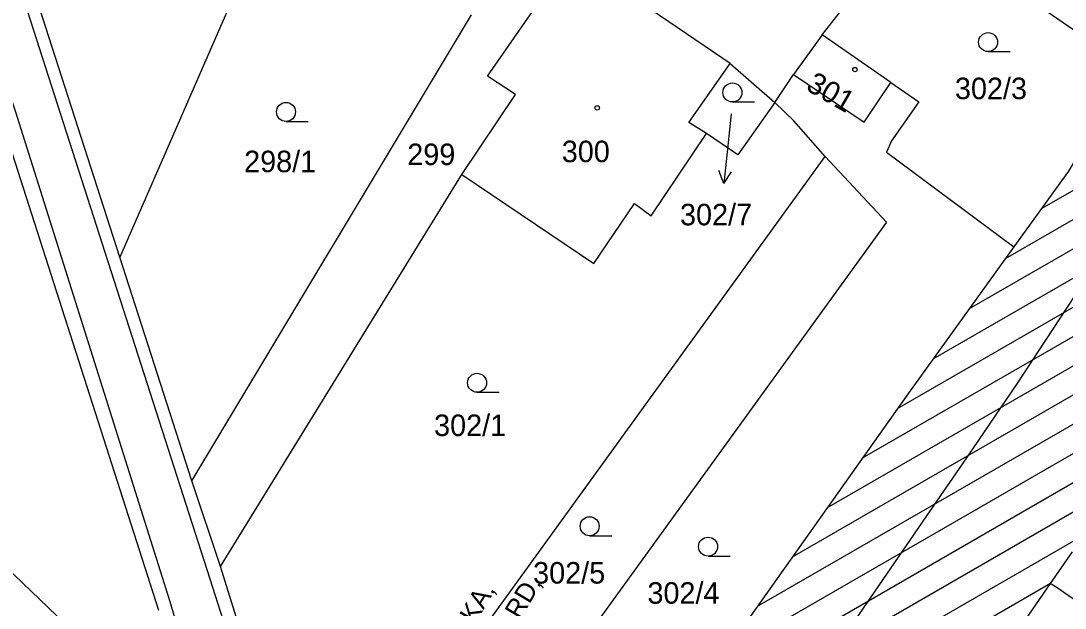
# Model space of a CAD drawing. Extents: x -558500 to -557517, y -1073973 to -1073051.
# Drawn here: x -558169.6 to -558087.2, y -1073349.6 to -1073303.2 of the extents above; entities that cross this region are included whole.
import ezdxf

# ---------------------------------------------------------------- set-up
doc = ezdxf.new("R2010")
doc.units = 0
for name, color, linetype in [('Hranice parcel', 7, 'Continuous'), ('Kolej', 7, 'Continuous'), ('Parcelní čísla', 7, 'Continuous'), ('Pop  PČ popisy', 7, 'Continuous'), ('Svazek obcí údolí Desné', 7, 'Continuous'), ('trasa_NN_popisky', 7, 'Continuous'), ('Značky budov', 7, 'Continuous'), ('Značky kultur', 7, 'Continuous')]:
    doc.layers.add(name, color=color, linetype=linetype)

msp = doc.modelspace()

# ---------------------------------------------------------------- linework, layer by layer
at = {"layer": 'Hranice parcel'}
for p, q in [((-558149, -1073292.52), (-558161.8, -1073321.91)), ((-558161.8, -1073321.91), (-558170.97, -1073293.42)), ((-558106.35, -1073304.33), (-558099.14, -1073295.15)), ((-558099.14, -1073295.15), (-558082.18, -1073306.93)), ((-558156.12, -1073339.58), (-558134.04, -1073302.76)), ((-558106.35, -1073304.33), (-558108.61, -1073307.47)), ((-558100.91, -1073308.09), (-558106.35, -1073304.33)), ((-558113.61, -1073306.59), (-558110.09, -1073309.68)), ((-558110.09, -1073309.68), (-558108.61, -1073307.47)), ((-558171.18, -1073310.99), (-558158.75, -1073349.79)), ((-558146.53, -1073369.85), (-558106.1, -1073313.94)), ((-558101.25, -1073313.61), (-558091.21, -1073321.1)), ((-558153.86, -1073346.35), (-558134.81, -1073315.38)), ((-558156.12, -1073339.58), (-558161.8, -1073321.91)), ((-558179.03, -1073338.54), (-558163.3, -1073353.56)), ((-558153.86, -1073346.35), (-558156.12, -1073339.58)), ((-558146.53, -1073369.85), (-558153.86, -1073346.35))]:
    msp.add_line(p, q, dxfattribs=at)
for points in [[(-558140.29, -1073392.34), (-558154.66, -1073347.35), (-558171.71, -1073294.39)], [(-558134.81, -1073315.38), (-558130.55, -1073309.06), (-558132.76, -1073307.6), (-558126.22, -1073298.15)], [(-558113.61, -1073306.59), (-558124.02, -1073299.5), (-558124.12, -1073299.64), (-558126.22, -1073298.15)], [(-558172.36, -1073303.47), (-558170.06, -1073310.34), (-558157.85, -1073349.12), (-558143.83, -1073396.83)], [(-558115.48, -1073312.12), (-558116.87, -1073311.27), (-558113.61, -1073306.59)], [(-558108.61, -1073307.47), (-558103.03, -1073311.24), (-558100.91, -1073308.09)], [(-558100.91, -1073308.09), (-558098.7, -1073309.62), (-558100.86, -1073312.72), (-558101.25, -1073313.61)], [(-558110.09, -1073309.68), (-558113.01, -1073313.83), (-558115.48, -1073312.12)], [(-558106.1, -1073313.94), (-558108.58, -1073311.13), (-558110.09, -1073309.68)], [(-558134.81, -1073315.38), (-558124.37, -1073322.4), (-558121.16, -1073317.67), (-558119.85, -1073318.64), (-558115.48, -1073312.12)], [(-558106.1, -1073313.94), (-558101.27, -1073319.14), (-558143.89, -1073378.07)], [(-558100.88, -1073366.68), (-558093.95, -1073371.49), (-558091.09, -1073367.38), (-558089.54, -1073368.47), (-558085.38, -1073362.53), (-558086.24, -1073361.96), (-558080.2, -1073353.3), (-558087.87, -1073347.97), (-558088.33, -1073347.7)]]:
    msp.add_lwpolyline(points, dxfattribs=at)
at = {"layer": 'Kolej'}
msp.add_lwpolyline([(-558164.779, -1073439.38), (-558155.66, -1073426.127), (-558147.216, -1073413.854), (-558143.692, -1073408.727), (-558141.06, -1073404.904), (-558137.302, -1073399.438), (-558134.569, -1073395.461), (-558131.717, -1073391.307), (-558124.893, -1073381.375), (-558115.4, -1073367.564), (-558106.183, -1073354.164), (-558097.487, -1073341.511), (-558095.261, -1073338.268), (-558090.946, -1073331.927), (-558084.696, -1073322.399), (-558079.035, -1073313.091), (-558073.774, -1073303.7), (-558068.675, -1073293.768)], dxfattribs=at)
at = {"layer": 'Pop  PČ popisy'}
for p, q in [((-558113.53, -1073310.57), (-558113.79, -1073313.11)), ((-558113.79, -1073313.11), (-558114.104, -1073316.095)), ((-558114.104, -1073316.095), (-558114.497, -1073315.046)), ((-558114.104, -1073316.095), (-558113.501, -1073315.151))]:
    msp.add_line(p, q, dxfattribs=at)
at = {"layer": 'Svazek obcí údolí Desné'}
for p, q in [((-558089.021, -1073318.064), (-558046.972, -1073293.788)), ((-558091.873, -1073322.02), (-558048.481, -1073296.968)), ((-558103.156, -1073337.772), (-558054.518, -1073309.691)), ((-558094.721, -1073325.974), (-558070.736, -1073312.126)), ((-558105.921, -1073341.678), (-558056.17, -1073312.954)), ((-558097.569, -1073329.928), (-558073.135, -1073315.821)), ((-558108.685, -1073345.583), (-558058.52, -1073316.62)), ((-558100.391, -1073333.867), (-558073.265, -1073318.205)), ((-558111.45, -1073349.489), (-558060.869, -1073320.286)), ((-558114.215, -1073353.394), (-558063.219, -1073323.952)), ((-558116.979, -1073357.3), (-558065.568, -1073327.618)), ((-558119.744, -1073361.206), (-558069.866, -1073332.409)), ((-558122.509, -1073365.111), (-558071.867, -1073335.873)), ((-558086.59, -1073345.2), (-558088.33, -1073347.7)), ((-558110.806, -1073360.664), (-558088.316, -1073347.679))]:
    msp.add_line(p, q, dxfattribs=at)
for points in [[(-558082.18, -1073306.93), (-558086.02, -1073313.63), (-558086.89, -1073315.11), (-558091.21, -1073321.1)], [(-558091.21, -1073321.1), (-558099.53, -1073332.65), (-558131.71, -1073378.11), (-558132.32, -1073380.12), (-558138.4, -1073389.94), (-558139.67, -1073391.56)], [(-558088.33, -1073347.7), (-558094.78, -1073357.07), (-558098.42, -1073362.32), (-558098.04, -1073362.58), (-558100.88, -1073366.68)]]:
    msp.add_lwpolyline(points, dxfattribs=at)
at = {"layer": 'Značky budov'}
for centre in [(-558103.757, -1073307.079), (-558124.107, -1073310.109)]:
    msp.add_circle(centre, 0.175, dxfattribs=at)
at = {"layer": 'Značky kultur'}
for p, q in [((-558093.243, -1073305.66), (-558091.493, -1073305.66)), ((-558113.433, -1073309.64), (-558111.683, -1073309.64)), ((-558148.683, -1073311.18), (-558146.933, -1073311.18)), ((-558133.593, -1073332.58), (-558131.843, -1073332.58)), ((-558124.703, -1073343.92), (-558122.953, -1073343.92)), ((-558115.353, -1073345.53), (-558113.603, -1073345.53))]:
    msp.add_line(p, q, dxfattribs=at)
for centre in [(-558093.243, -1073304.91), (-558113.433, -1073308.89), (-558148.683, -1073310.43), (-558133.593, -1073331.83), (-558124.703, -1073343.17), (-558115.353, -1073344.78)]:
    msp.add_circle(centre, 0.75, dxfattribs=at)

# ---------------------------------------------------------------- texts
at = {"layer": 'Parcelní čísla'}
msp.add_text('301', height=1.7, rotation=330, dxfattribs=at).set_placement((-558107.718, -1073308.643))
for s, p in [('302/3', (-558095.858, -1073309.42)), ('299', (-558139.105, -1073314.63)), ('300', (-558126.905, -1073314.4)), ('298/1', (-558151.988, -1073315.19)), ('302/7', (-558117.568, -1073319.39)), ('302/1', (-558136.988, -1073336.04)), ('302/5', (-558129.166, -1073347.7)), ('302/4', (-558120.141, -1073349.29))]:
    msp.add_text(s, height=1.7, dxfattribs=at).set_placement(p)
at = {"layer": 'trasa_NN_popisky'}
for s, p in [('HLOUBKOVÝ ZEMNIČ NEREZ V4A, PŘIPOJIT NA RD,', (-558154.034, -1073390.512)), ('ZEMNÍCÍ PÁSEK NEREZ V4A, ZJ - ZEMNÍCÍ JÍMKA, ', (-558156.513, -1073389.032))]:
    msp.add_text(s, height=1.5, rotation=59.15905, dxfattribs=at).set_placement(p)

doc.saveas('drawing.dxf')
